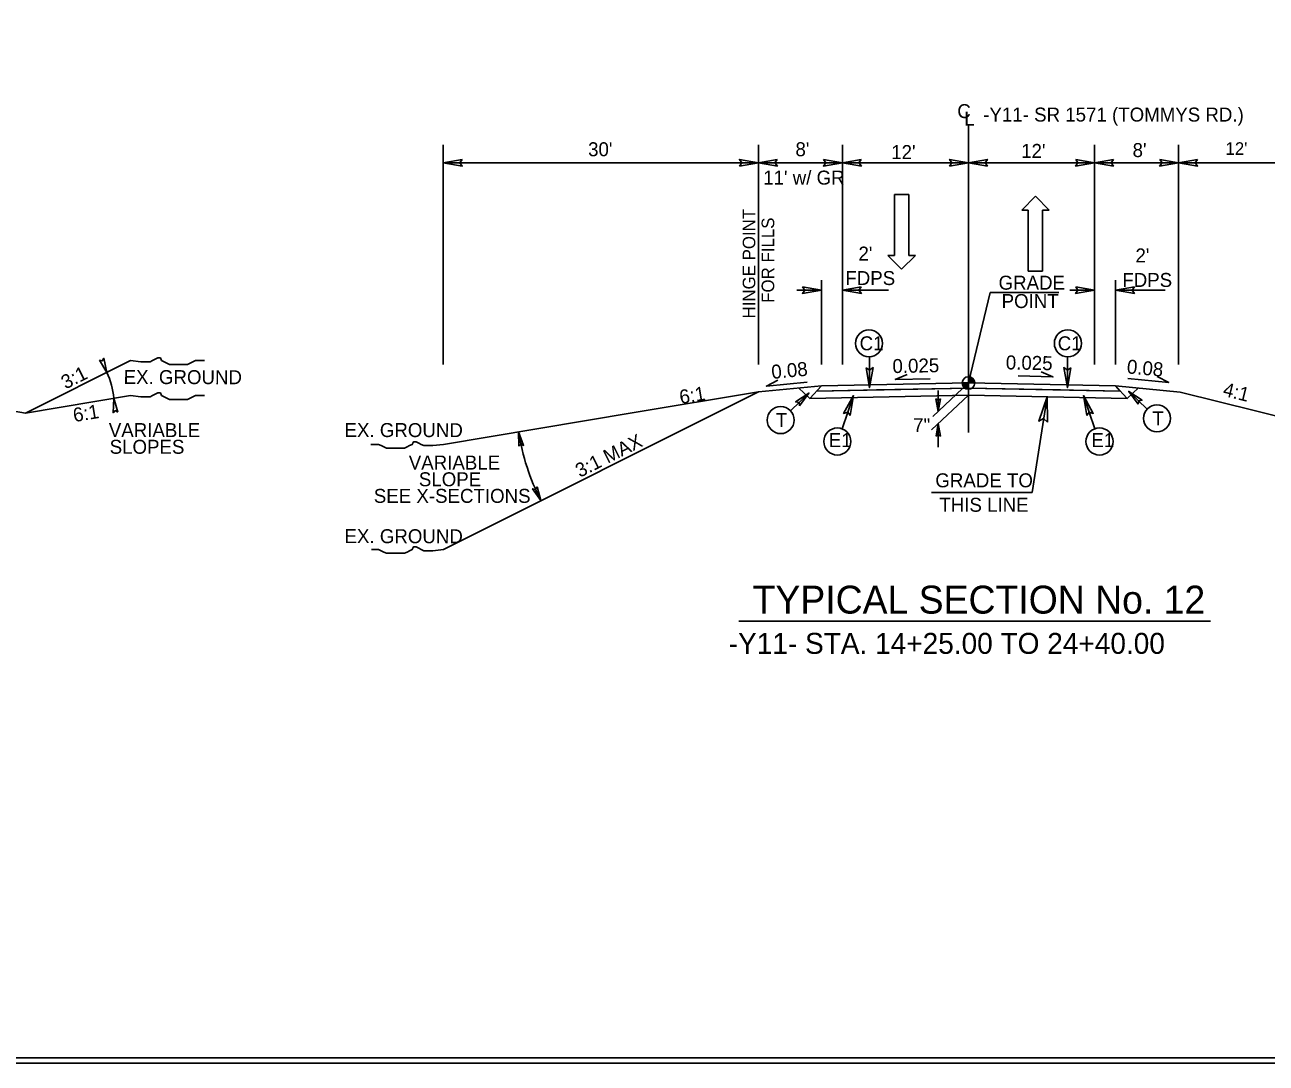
# Model space of a CAD drawing. Extents: x 2320980 to 2456309, y 595047 to 606177.
# Drawn here: x 2455851.9 to 2455970.1, y 596088.6 to 596187.4 of the extents above; entities that cross this region are included whole.
import ezdxf

# ---------------------------------------------------------------- set-up
doc = ezdxf.new("R2010")
doc.units = 0
for name, color, linetype in [('Old_Level_1', 7, 'Continuous'), ('Old_Level_11', 7, 'Continuous'), ('Old_Level_2', 7, 'Continuous'), ('Old_Level_20', 7, 'Continuous'), ('Old_Level_21', 7, 'Continuous'), ('Old_Level_3', 7, 'Continuous'), ('Prop Dimension', 7, 'Continuous'), ('Prop Dimension Text', 7, 'Continuous'), ('Prop Lane Arrow CELL', 7, 'Continuous'), ('Prop Terminator CELL', 7, 'Continuous'), ('Sheet Plan CELL', 7, 'Continuous'), ('Sheet Plot Border Inside CELL', 7, 'Continuous'), ('Typical Grade Point Symbol CELL', 7, 'Continuous'), ('Typical Hinge Slope Arterial CELL', 7, 'Continuous'), ('Typical ID Circle CELL', 7, 'Continuous'), ('Typical Pavement Slope CELL', 7, 'Continuous'), ('Typical Pavement Slope Information CELL', 7, 'Continuous'), ('Typical Terminator CELL', 7, 'Continuous')]:
    doc.layers.add(name, color=color, linetype=linetype)

msp = doc.modelspace()

# ---------------------------------------------------------------- linework, layer by layer
at = {"layer": 'Old_Level_1'}
for p, q in [((2455941.77, 596153.31), (2455943.84, 596161.91)), ((2455943.84, 596161.91), (2455950.39, 596161.91)), ((2455927.77, 596153.03), (2455921.77, 596152.47)), ((2455926.68, 596151.84), (2455925.6, 596152.84)), ((2455926.68, 596151.84), (2455927.77, 596153.03)), ((2455926.68, 596151.84), (2455941.77, 596152.15)), ((2455956.87, 596151.84), (2455941.77, 596152.15)), ((2455955.77, 596153.03), (2455961.92, 596152.45)), ((2455956.87, 596151.84), (2455955.77, 596153.03)), ((2455956.87, 596151.84), (2455957.95, 596152.84))]:
    msp.add_line(p, q, dxfattribs=at)
at = {"layer": 'Old_Level_11'}
msp.add_lwpolyline([(2455949.29, 596149.57), (2455949.26, 596152), (2455948.46, 596149.68), (2455948.93, 596149.92)], close=True, dxfattribs=at)
at = {"layer": 'Old_Level_21'}
for p, q in [((2455891.77, 596155.08), (2455891.77, 596175.96)), ((2455921.77, 596155.08), (2455921.77, 596175.96)), ((2455929.77, 596155.08), (2455929.77, 596175.96)), ((2455953.77, 596155.08), (2455953.77, 596175.96)), ((2455961.77, 596155.08), (2455961.77, 596175.96)), ((2455921.77, 596174.27), (2455891.77, 596174.27)), ((2455921.77, 596174.27), (2455929.77, 596174.27)), ((2455929.77, 596174.27), (2455941.77, 596174.27)), ((2455953.77, 596174.27), (2455941.77, 596174.27)), ((2455953.77, 596174.27), (2455961.77, 596174.27)), ((2455927.77, 596155.08), (2455927.77, 596163.1)), ((2455955.77, 596155.08), (2455955.77, 596163.1)), ((2455927.77, 596162.15), (2455925.44, 596162.15)), ((2455934.16, 596162.15), (2455929.77, 596162.15)), ((2455951.44, 596162.15), (2455953.77, 596162.15)), ((2455955.77, 596162.15), (2455960.49, 596162.15)), ((2455947.84, 596142.88), (2455949.26, 596152)), ((2455938.26, 596142.88), (2455947.84, 596142.88))]:
    msp.add_line(p, q, dxfattribs=at)
at = {"layer": 'Old_Level_3'}
for p, q in [((2455941.77, 596152.83), (2455927.32, 596152.54)), ((2455941.77, 596152.83), (2455956.22, 596152.54)), ((2455919.91, 596130.63), (2455964.83, 596130.63))]:
    msp.add_line(p, q, dxfattribs=at)
at = {"layer": 'Prop Dimension'}
for p, q in [((2455973.77, 596174.27), (2455961.77, 596174.27)), ((2455941.77, 596153.31), (2455938.39, 596150.13)), ((2455941.77, 596153.31), (2455938.39, 596150.13)), ((2455941.77, 596152.16), (2455938.27, 596148.86)), ((2455941.77, 596152.16), (2455938.27, 596148.86)), ((2455938.89, 596152.6), (2455938.89, 596150.6)), ((2455938.89, 596152.6), (2455938.89, 596150.6)), ((2455938.89, 596149.45), (2455938.89, 596147.2)), ((2455938.89, 596149.45), (2455938.89, 596147.2))]:
    msp.add_line(p, q, dxfattribs=at)
at = {"layer": 'Prop Dimension Text'}
for p, q in [((2455941.77, 596148.61), (2455941.77, 596177.81)), ((2455924.83, 596150.67), (2455926.59, 596152.35)), ((2455958.79, 596150.83), (2455957.03, 596152.51))]:
    msp.add_line(p, q, dxfattribs=at)
for points in [[(2455926.42, 596153.39), (2455922.53, 596153.02), (2455923.63, 596153.58)], [(2455938.13, 596153.72), (2455934.81, 596153.63), (2455935.94, 596154.12)], [(2455946.5, 596153.98), (2455949.82, 596153.89), (2455948.69, 596154.38)], [(2455956.95, 596153.75), (2455960.84, 596153.37), (2455959.74, 596153.94)]]:
    msp.add_lwpolyline(points, dxfattribs=at)
for centre in [(2455932.3, 596157.08), (2455951.24, 596157.08), (2455923.89, 596149.78), (2455959.72, 596149.94), (2455929.29, 596147.74), (2455954.25, 596147.74)]:
    msp.add_circle(centre, 1.29, dxfattribs=at)
at = {"layer": 'Prop Lane Arrow CELL'}
for p, q in [((2455934.72, 596171.26), (2455934.72, 596165.44)), ((2455936.09, 596171.26), (2455934.72, 596171.26)), ((2455936.09, 596165.44), (2455936.09, 596171.26)), ((2455948.17, 596171.08), (2455946.84, 596169.77)), ((2455949.46, 596169.77), (2455948.17, 596171.08)), ((2455946.84, 596169.77), (2455947.46, 596169.77)), ((2455947.46, 596169.77), (2455947.46, 596163.95)), ((2455948.83, 596163.95), (2455948.83, 596169.77)), ((2455948.83, 596169.77), (2455949.46, 596169.77)), ((2455934.72, 596165.44), (2455934.1, 596165.44)), ((2455934.1, 596165.44), (2455935.39, 596164.13)), ((2455935.39, 596164.13), (2455936.72, 596165.44)), ((2455936.72, 596165.44), (2455936.09, 596165.44)), ((2455947.46, 596163.95), (2455948.83, 596163.95))]:
    msp.add_line(p, q, dxfattribs=at)
at = {"layer": 'Prop Terminator CELL'}
for points in [[(2455939.1, 596151.8), (2455938.89, 596150.6), (2455938.68, 596151.8), (2455938.89, 596151.65)], [(2455939.1, 596151.8), (2455938.89, 596150.6), (2455938.68, 596151.8), (2455938.89, 596151.65)], [(2455938.69, 596148.26), (2455938.89, 596149.45), (2455939.11, 596148.25), (2455938.89, 596148.4)], [(2455938.69, 596148.26), (2455938.89, 596149.45), (2455939.11, 596148.25), (2455938.89, 596148.4)]]:
    msp.add_lwpolyline(points, close=True, dxfattribs=at)
at = {"layer": 'Sheet Plan CELL'}
for points in [[(2456042.11, 596299.08), (2455742.1, 596299.08), (2455742.1, 596089.08), (2456042.11, 596089.08)], [(2455742.1, 596089.08), (2455742.1, 596299.07), (2456002.1, 596299.08), (2456002.1, 596269.07), (2456042.11, 596269.06), (2456042.11, 596089.08)]]:
    msp.add_lwpolyline(points, close=True, dxfattribs=at)
at = {"layer": 'Sheet Plot Border Inside CELL'}
msp.add_lwpolyline([(2455711.41, 596088.57), (2456044.6, 596088.58), (2456044.61, 596299.57), (2455711.41, 596299.57)], close=True, dxfattribs=at)
at = {"layer": 'Typical Grade Point Symbol CELL'}
for p, q in [((2455941.18, 596153.31), (2455941.77, 596153.31)), ((2455941.77, 596153.31), (2455941.77, 596153.91)), ((2455942.37, 596153.31), (2455941.77, 596153.31)), ((2455941.77, 596152.71), (2455941.77, 596153.31)), ((2455941.77, 596153.31), (2455941.77, 596152.71))]:
    msp.add_line(p, q, dxfattribs=at)
for points in [[(2455941.18, 596153.31), (2455941.18, 596153.25)], [(2455941.19, 596153.31), (2455941.19, 596153.18)], [(2455941.2, 596153.31), (2455941.2, 596153.13)], [(2455941.21, 596153.31), (2455941.21, 596153.1)], [(2455941.23, 596153.31), (2455941.23, 596153.07)], [(2455941.24, 596153.31), (2455941.24, 596153.04)], [(2455941.25, 596153.31), (2455941.25, 596153.02)], [(2455941.26, 596153.31), (2455941.26, 596153)], [(2455941.27, 596153.31), (2455941.27, 596152.98)], [(2455941.29, 596153.31), (2455941.29, 596152.96)], [(2455941.3, 596153.31), (2455941.3, 596152.95)], [(2455941.31, 596153.31), (2455941.31, 596152.93)], [(2455941.32, 596153.31), (2455941.32, 596152.92)], [(2455941.33, 596153.31), (2455941.33, 596152.91)], [(2455941.34, 596153.31), (2455941.34, 596152.89)], [(2455941.36, 596153.31), (2455941.36, 596152.88)], [(2455941.37, 596153.31), (2455941.37, 596152.87)], [(2455941.38, 596153.31), (2455941.38, 596152.86)], [(2455941.39, 596153.31), (2455941.39, 596152.85)], [(2455941.4, 596153.31), (2455941.4, 596152.84)], [(2455941.42, 596153.31), (2455941.42, 596152.83)], [(2455941.43, 596153.31), (2455941.43, 596152.82)], [(2455941.44, 596153.31), (2455941.44, 596152.82)], [(2455941.45, 596153.31), (2455941.45, 596152.81)], [(2455941.46, 596153.31), (2455941.46, 596152.8)], [(2455941.48, 596153.31), (2455941.48, 596152.79)], [(2455941.49, 596153.31), (2455941.49, 596152.79)], [(2455941.5, 596153.31), (2455941.5, 596152.78)], [(2455941.51, 596153.31), (2455941.51, 596152.77)], [(2455941.52, 596153.31), (2455941.52, 596152.77)], [(2455941.54, 596153.31), (2455941.54, 596152.76)], [(2455941.55, 596153.31), (2455941.55, 596152.76)], [(2455941.56, 596153.31), (2455941.56, 596152.75)], [(2455941.57, 596153.31), (2455941.57, 596152.75)], [(2455941.58, 596153.31), (2455941.58, 596152.75)], [(2455941.59, 596153.31), (2455941.59, 596152.74)], [(2455941.61, 596153.31), (2455941.61, 596152.74)], [(2455941.62, 596153.31), (2455941.62, 596152.73)], [(2455941.63, 596153.31), (2455941.63, 596152.73)], [(2455941.64, 596153.31), (2455941.64, 596152.73)], [(2455941.65, 596153.31), (2455941.65, 596152.73)], [(2455941.67, 596153.31), (2455941.67, 596152.72)], [(2455941.68, 596153.31), (2455941.68, 596152.72)], [(2455941.69, 596153.31), (2455941.69, 596152.72)], [(2455941.7, 596153.31), (2455941.7, 596152.72)], [(2455941.71, 596153.31), (2455941.71, 596152.72)], [(2455941.73, 596153.31), (2455941.73, 596152.72)], [(2455941.74, 596153.31), (2455941.74, 596152.72)], [(2455941.75, 596153.31), (2455941.75, 596152.71)], [(2455941.76, 596153.31), (2455941.76, 596152.71), (2455941.76, 596152.71)], [(2455941.78, 596153.91), (2455941.78, 596153.91), (2455941.78, 596153.31)], [(2455941.79, 596153.91), (2455941.79, 596153.31)], [(2455941.8, 596153.9), (2455941.8, 596153.31)], [(2455941.81, 596153.9), (2455941.81, 596153.31)], [(2455941.82, 596153.9), (2455941.82, 596153.31)], [(2455941.84, 596153.9), (2455941.84, 596153.31)], [(2455941.85, 596153.9), (2455941.85, 596153.31)], [(2455941.86, 596153.9), (2455941.86, 596153.31)], [(2455941.87, 596153.9), (2455941.87, 596153.31)], [(2455941.88, 596153.9), (2455941.88, 596153.31)], [(2455941.89, 596153.89), (2455941.89, 596153.31)], [(2455941.91, 596153.89), (2455941.91, 596153.31)], [(2455941.92, 596153.89), (2455941.92, 596153.31)], [(2455941.93, 596153.88), (2455941.93, 596153.31)], [(2455941.94, 596153.88), (2455941.94, 596153.31)], [(2455941.95, 596153.88), (2455941.95, 596153.31)], [(2455941.97, 596153.87), (2455941.97, 596153.31)], [(2455941.98, 596153.87), (2455941.98, 596153.31)], [(2455941.99, 596153.86), (2455941.99, 596153.31)], [(2455942, 596153.86), (2455942, 596153.31)], [(2455942.01, 596153.85), (2455942.01, 596153.31)], [(2455942.03, 596153.85), (2455942.03, 596153.31)], [(2455942.04, 596153.84), (2455942.04, 596153.31)], [(2455942.05, 596153.84), (2455942.05, 596153.31)], [(2455942.06, 596153.83), (2455942.06, 596153.31)], [(2455942.07, 596153.82), (2455942.07, 596153.31)], [(2455942.09, 596153.82), (2455942.09, 596153.31)], [(2455942.1, 596153.81), (2455942.1, 596153.31)], [(2455942.11, 596153.8), (2455942.11, 596153.31)], [(2455942.12, 596153.79), (2455942.12, 596153.31)], [(2455942.13, 596153.78), (2455942.13, 596153.31)], [(2455942.15, 596153.77), (2455942.15, 596153.31)], [(2455942.16, 596153.76), (2455942.16, 596153.31)], [(2455942.17, 596153.75), (2455942.17, 596153.31)], [(2455942.18, 596153.74), (2455942.18, 596153.31)], [(2455942.19, 596153.73), (2455942.19, 596153.31)], [(2455942.2, 596153.72), (2455942.2, 596153.31)], [(2455942.22, 596153.7), (2455942.22, 596153.31)], [(2455942.23, 596153.69), (2455942.23, 596153.31)], [(2455942.24, 596153.68), (2455942.24, 596153.31)], [(2455942.25, 596153.66), (2455942.25, 596153.31)], [(2455942.26, 596153.64), (2455942.26, 596153.31)], [(2455942.28, 596153.62), (2455942.28, 596153.31)], [(2455942.29, 596153.6), (2455942.29, 596153.31)], [(2455942.3, 596153.58), (2455942.3, 596153.31)], [(2455942.31, 596153.56), (2455942.31, 596153.31)], [(2455942.32, 596153.53), (2455942.32, 596153.31)], [(2455942.34, 596153.5), (2455942.34, 596153.31)], [(2455942.35, 596153.46), (2455942.35, 596153.31)], [(2455942.36, 596153.39), (2455942.36, 596153.31)]]:
    msp.add_lwpolyline(points, dxfattribs=at)
msp.add_circle((2455941.77, 596153.31), 0.595, dxfattribs=at)
for start, end in [(179.9905, 269.9905), (359.9905, 89.9905)]:
    msp.add_arc((2455941.77, 596153.31), 0.595, start, end, dxfattribs=at)
at = {"layer": 'Typical Hinge Slope Arterial CELL'}
for p, q in [((2455862.01, 596155.45), (2455852.01, 596150.45)), ((2455852.01, 596150.45), (2455840.01, 596152.45)), ((2455862.01, 596152.12), (2455852.01, 596150.45)), ((2455891.78, 596137.47), (2455921.77, 596152.47)), ((2455909.77, 596150.47), (2455921.77, 596152.47)), ((2455973.77, 596149.49), (2455961.92, 596152.45)), ((2455891.78, 596147.47), (2455909.77, 596150.47))]:
    msp.add_line(p, q, dxfattribs=at)
for points in [[(2455862.01, 596155.45), (2455862.99, 596155.33), (2455863.24, 596155.33), (2455863.61, 596155.33), (2455863.86, 596155.33), (2455864.1, 596155.45), (2455864.35, 596155.58), (2455864.59, 596155.7), (2455864.84, 596155.7), (2455864.96, 596155.45), (2455865.21, 596155.33), (2455865.46, 596155.21), (2455865.7, 596155.08), (2455865.95, 596155.08), (2455866.2, 596155.08), (2455866.44, 596155.08), (2455866.69, 596155.08), (2455866.94, 596155.08), (2455867.18, 596155.08), (2455867.43, 596155.08), (2455867.67, 596155.21), (2455867.92, 596155.33), (2455868.17, 596155.45), (2455868.54, 596155.45), (2455868.78, 596155.45), (2455869.03, 596155.45)], [(2455862.01, 596152.12), (2455862.99, 596152), (2455863.24, 596152), (2455863.61, 596152), (2455863.86, 596152), (2455864.1, 596152.12), (2455864.35, 596152.24), (2455864.59, 596152.37), (2455864.84, 596152.37), (2455864.96, 596152.12), (2455865.21, 596152), (2455865.46, 596151.87), (2455865.7, 596151.75), (2455865.95, 596151.75), (2455866.2, 596151.75), (2455866.44, 596151.75), (2455866.69, 596151.75), (2455866.94, 596151.75), (2455867.18, 596151.75), (2455867.43, 596151.75), (2455867.67, 596151.87), (2455867.92, 596152), (2455868.17, 596152.12), (2455868.54, 596152.12), (2455868.78, 596152.12), (2455869.03, 596152.12)], [(2455891.78, 596147.47), (2455890.79, 596147.35), (2455890.54, 596147.35), (2455890.17, 596147.35), (2455889.93, 596147.35), (2455889.68, 596147.47), (2455889.44, 596147.59), (2455889.19, 596147.72), (2455888.94, 596147.72), (2455888.82, 596147.47), (2455888.57, 596147.35), (2455888.33, 596147.22), (2455888.08, 596147.1), (2455887.83, 596147.1), (2455887.59, 596147.1), (2455887.34, 596147.1), (2455887.09, 596147.1), (2455886.85, 596147.1), (2455886.6, 596147.1), (2455886.36, 596147.1), (2455886.11, 596147.22), (2455885.86, 596147.35), (2455885.62, 596147.47), (2455885.25, 596147.47), (2455885, 596147.47), (2455884.88, 596147.47)], [(2455891.78, 596137.47), (2455890.79, 596137.35), (2455890.54, 596137.35), (2455890.17, 596137.35), (2455889.93, 596137.35), (2455889.68, 596137.47), (2455889.44, 596137.59), (2455889.19, 596137.72), (2455888.94, 596137.72), (2455888.82, 596137.47), (2455888.57, 596137.35), (2455888.33, 596137.22), (2455888.08, 596137.1), (2455887.83, 596137.1), (2455887.59, 596137.1), (2455887.34, 596137.1), (2455887.09, 596137.1), (2455886.85, 596137.1), (2455886.6, 596137.1), (2455886.36, 596137.1), (2455886.11, 596137.22), (2455885.86, 596137.35), (2455885.62, 596137.47), (2455885.25, 596137.47), (2455885, 596137.47), (2455884.95, 596137.47)]]:
    msp.add_lwpolyline(points, dxfattribs=at)
for centre, radius, start, end in [((2455852.71, 596151.07), 7.74, 5.8103, 24.8127), ((2455921.77, 596152.47), 23.16, 189.4624, 206.565)]:
    msp.add_arc(centre, radius, start, end, dxfattribs=at)
at = {"layer": 'Typical ID Circle CELL'}
for p, q in [((2455932.35, 596155.81), (2455932.35, 596152.87)), ((2455951.19, 596155.81), (2455951.19, 596152.87)), ((2455929.74, 596148.96), (2455930.83, 596152.11)), ((2455953.81, 596148.96), (2455952.72, 596152.11))]:
    msp.add_line(p, q, dxfattribs=at)
at = {"layer": 'Typical Pavement Slope CELL'}
for p, q in [((2455927.77, 596153.03), (2455941.77, 596153.31)), ((2455941.77, 596153.31), (2455927.77, 596153.03)), ((2455941.77, 596153.31), (2455955.77, 596153.03)), ((2455955.77, 596153.03), (2455941.77, 596153.31)), ((2455941.77, 596153.31), (2455941.77, 596152.83)), ((2455941.77, 596153.31), (2455941.77, 596152.83)), ((2455927.32, 596152.54), (2455927.77, 596153.03)), ((2455941.77, 596152.83), (2455933.02, 596152.65)), ((2455941.77, 596152.83), (2455950.52, 596152.65)), ((2455956.22, 596152.54), (2455955.77, 596153.03))]:
    msp.add_line(p, q, dxfattribs=at)
for points in [[(2455933.02, 596152.65), (2455931.77, 596152.63), (2455927.32, 596152.54)], [(2455950.52, 596152.65), (2455951.77, 596152.63), (2455956.22, 596152.54)]]:
    msp.add_lwpolyline(points, dxfattribs=at)
at = {"layer": 'Typical Terminator CELL'}
for points in [[(2455893.57, 596174.58), (2455891.77, 596174.27), (2455893.58, 596173.95), (2455893.35, 596174.27)], [(2455919.98, 596173.96), (2455921.77, 596174.27), (2455919.97, 596174.59), (2455920.2, 596174.27)], [(2455923.57, 596174.58), (2455921.77, 596174.27), (2455923.58, 596173.95), (2455923.35, 596174.27)], [(2455927.98, 596174.58), (2455929.77, 596174.27), (2455927.97, 596173.95), (2455928.2, 596174.27)], [(2455931.57, 596174.58), (2455929.77, 596174.27), (2455931.58, 596173.95), (2455931.35, 596174.27)], [(2455939.98, 596173.96), (2455941.77, 596174.27), (2455939.97, 596174.59), (2455940.2, 596174.27)], [(2455943.57, 596173.96), (2455941.77, 596174.27), (2455943.58, 596174.59), (2455943.35, 596174.27)], [(2455951.98, 596174.58), (2455953.77, 596174.27), (2455951.97, 596173.95), (2455952.2, 596174.27)], [(2455955.57, 596174.58), (2455953.77, 596174.27), (2455955.58, 596173.95), (2455955.35, 596174.27)], [(2455959.98, 596174.58), (2455961.77, 596174.27), (2455959.97, 596173.95), (2455960.2, 596174.27)], [(2455963.57, 596174.58), (2455961.77, 596174.27), (2455963.58, 596173.95), (2455963.35, 596174.27)], [(2455925.98, 596162.46), (2455927.77, 596162.15), (2455925.97, 596161.83), (2455926.2, 596162.15)], [(2455931.57, 596162.46), (2455929.77, 596162.15), (2455931.58, 596161.83), (2455931.35, 596162.15)], [(2455951.98, 596162.46), (2455953.77, 596162.15), (2455951.97, 596161.83), (2455952.2, 596162.15)], [(2455957.57, 596162.46), (2455955.77, 596162.15), (2455957.58, 596161.83), (2455957.35, 596162.15)], [(2455859.03, 596155.49), (2455859.74, 596154.32), (2455859.46, 596155.67), (2455859.3, 596155.42)], [(2455932.03, 596154.76), (2455932.35, 596152.87), (2455932.69, 596154.77), (2455932.35, 596154.53)], [(2455951.52, 596154.76), (2455951.19, 596152.87), (2455950.85, 596154.77), (2455951.19, 596154.53)], [(2455925.68, 596151.13), (2455926.59, 596152.35), (2455925.31, 596151.51), (2455925.64, 596151.45)], [(2455930.52, 596150.21), (2455930.83, 596152.11), (2455929.89, 596150.42), (2455930.28, 596150.54)], [(2455953.03, 596150.21), (2455952.72, 596152.11), (2455953.66, 596150.42), (2455953.26, 596150.54)], [(2455957.93, 596151.29), (2455957.03, 596152.51), (2455958.3, 596151.66), (2455957.98, 596151.6)], [(2455860.8, 596150.54), (2455860.41, 596151.85), (2455860.33, 596150.48), (2455860.55, 596150.68)], [(2455898.96, 596147.29), (2455898.93, 596148.66), (2455899.42, 596147.37), (2455899.16, 596147.5)], [(2455900.7, 596143.43), (2455901.06, 596142.11), (2455900.27, 596143.24), (2455900.56, 596143.18)]]:
    msp.add_lwpolyline(points, close=True, dxfattribs=at)

# ---------------------------------------------------------------- texts
at = {"layer": 'Old_Level_1'}
for s, p in [('GRADE', (2455944.64, 596162.19)), ('POINT', (2455944.93, 596160.44))]:
    msp.add_text(s, height=1.33, dxfattribs=at).set_placement(p)
for p in [(2455861.34, 596153.21), (2455882.37, 596148.17), (2455882.37, 596138.07)]:
    msp.add_text('EX. GROUND', height=1.33, rotation=359.9103, dxfattribs=at).set_placement(p)
at = {"layer": 'Old_Level_2'}
for s, height, p in [('TYPICAL SECTION No. 12', 2.66, (2455921.22, 596131.36)), ('-Y11- STA. 14+25.00 TO 24+40.00', 1.995, (2455918.95, 596127.53))]:
    msp.add_text(s, height=height, dxfattribs=at).set_placement(p)
at = {"layer": 'Old_Level_20'}
for s, p in [('C1', (2455931.41, 596156.42)), ('C1', (2455950.27, 596156.42)), ('T', (2455923.43, 596149.12)), ('T', (2455959.28, 596149.27)), ('E1', (2455928.48, 596147.21)), ('E1', (2455953.47, 596147.21))]:
    msp.add_text(s, height=1.33, dxfattribs=at).set_placement(p)
at = {"layer": 'Old_Level_21'}
for s, rotation, p in [('C', 0.0002, (2455940.71, 596178.52)), ('L', 0.0002, (2455941.37, 596177.81)), ("2'", 359.9998, (2455931.3, 596164.96)), ("2'", 0.0002, (2455957.67, 596164.78)), ('FDPS', 359.9998, (2455930.05, 596162.63)), ('FDPS', 0.0002, (2455956.42, 596162.45)), ('0.025', 1.1456, (2455934.55, 596154.25)), ('0.025', 358.8544, (2455945.32, 596154.61)), ('0.08', 5.3417, (2455923.07, 596153.69)), ('0.08', 354.6583, (2455956.81, 596154.23))]:
    msp.add_text(s, height=1.33, rotation=rotation, dxfattribs=at).set_placement(p)
for s, p in [('-Y11- SR 1571 (TOMMYS RD.)', (2455943.18, 596178.19)), ("30'", (2455905.56, 596174.89)), ("8'", (2455925.3, 596174.89)), ("12'", (2455934.42, 596174.62)), ("12'", (2455946.79, 596174.73)), ("8'", (2455957.4, 596174.81)), ("11' w/ GR", (2455922.23, 596172.19)), ('GRADE TO', (2455938.62, 596143.38)), ('THIS LINE', (2455939, 596141.05))]:
    msp.add_text(s, height=1.33, dxfattribs=at).set_placement(p)
at = {"layer": 'Prop Dimension Text'}
for s, rotation, p in [("12'", 0.0002, (2455966.24, 596175.02)), ('HINGE POINT', 90, (2455921.48, 596159.45)), ('FOR FILLS', 90, (2455923.28, 596160.94))]:
    msp.add_text(s, height=1.2, rotation=rotation, dxfattribs=at).set_placement(p)
at = {"layer": 'Typical Hinge Slope Arterial CELL'}
for s, rotation, p in [('3:1', 26.565, (2455855.81, 596152.68)), ('6:1', 9.4623, (2455914.37, 596151.3)), ('4:1', 345.9638, (2455965.92, 596152.11)), ('6:1', 9.4635, (2455856.64, 596149.58)), ('3:1 MAX', 26.5651, (2455904.77, 596144.28))]:
    msp.add_text(s, height=1.33, rotation=rotation, dxfattribs=at).set_placement(p)
for s, p in [('VARIABLE ', (2455859.93, 596148.16)), ('SLOPES', (2455860.01, 596146.57)), ('VARIABLE ', (2455888.49, 596145.07)), ('SLOPE', (2455889.45, 596143.48)), ('SEE X-SECTIONS', (2455885.16, 596141.9))]:
    msp.add_text(s, height=1.33, dxfattribs=at).set_placement(p)
at = {"layer": 'Typical Pavement Slope Information CELL'}
msp.add_text('7"', height=1.33, dxfattribs=at).set_placement((2455936.51, 596148.63))

doc.saveas('drawing.dxf')
